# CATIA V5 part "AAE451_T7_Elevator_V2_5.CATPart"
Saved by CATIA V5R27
Part number: Elevator
Bounding box of the stored display mesh (mm): x 0 to 69.698, y -12.436 to 0.05, z -229.965 to 0
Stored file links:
  W:\AAE 451\AAE451_T7_TailAssembly_V2\AAE451_T7_Elevator_V2_5.CATPart
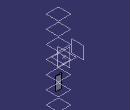
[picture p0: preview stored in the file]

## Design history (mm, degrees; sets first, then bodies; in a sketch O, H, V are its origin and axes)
Set1 "GeometryFromExcel"
  Point1: (1, 0.001, 0)
  Point2: (0.95, 0.0067, 0)
  Point3: (0.9, 0.0121, 0)
  Point4: (0.8, 0.0219, 0)
  Point5: (0.7, 0.0305, 0)
  Point6: (0.6, 0.038, 0)
  Point7: (0.5, 0.0441, 0)
  Point8: (0.4, 0.0484, 0)
  Point9: (0.3, 0.05, 0)
  Point10: (0.25, 0.0495, 0)
  Point11: (0.2, 0.0478, 0)
  Point12: (0.15, 0.0445, 0)
  Point13: (0.1, 0.039, 0)
  Point14: (0.075, 0.035, 0)
  Point15: (0.05, 0.0296, 0)
  Point16: (0.025, 0.0218, 0)
  Point17: (0.0125, 0.0158, 0)
  Point18: (0, 0, 0)
  Point19: (0.0125, -0.0158, 0)
  Point20: (0.025, -0.0218, 0)
  Point21: (0.05, -0.0296, 0)
  Point22: (0.075, -0.035, 0)
  Point23: (0.1, -0.039, 0)
  Point24: (0.15, -0.0445, 0)
  Point25: (0.2, -0.0478, 0)
  Point26: (0.25, -0.0495, 0)
  Point27: (0.3, -0.05, 0)
  Point28: (0.4, -0.0484, 0)
  Point29: (0.5, -0.0441, 0)
  Point30: (0.6, -0.038, 0)
  Point31: (0.7, -0.0305, 0)
  Point32: (0.8, -0.0219, 0)
  Point33: (0.9, -0.0121, 0)
  Point34: (0.95, -0.0067, 0)
  Point35: (1, -0.001, 0)
  Point36: (1, 0.001, 0)
  Point37: (0.95, 0.0067, 0)
  Point38: (0.9, 0.0121, 0)
  Point39: (0.8, 0.0219, 0)
  Point40: (0.7, 0.0305, 0)
  Point41: (0.6, 0.038, 0)
  Point42: (0.5, 0.0441, 0)
  Point43: (0.4, 0.0484, 0)
  Point44: (0.3, 0.05, 0)
  Point45: (0.25, 0.0495, 0)
  Point46: (0.2, 0.0478, 0)
  Point47: (0.15, 0.0445, 0)
  Point48: (0.1, 0.039, 0)
  Point49: (0.075, 0.035, 0)
  Point50: (0.05, 0.0296, 0)
  Point51: (0.025, 0.0218, 0)
  Point52: (0.0125, 0.0158, 0)
  Point53: (0, 0, 0)
  Point54: (0.0125, -0.0158, 0)
  Point55: (0.025, -0.0218, 0)
  Point56: (0.05, -0.0296, 0)
  Point57: (0.075, -0.035, 0)
  Point58: (0.1, -0.039, 0)
  Point59: (0.15, -0.0445, 0)
  Point60: (0.2, -0.0478, 0)
  Point61: (0.25, -0.0495, 0)
  Point62: (0.3, -0.05, 0)
  Point63: (0.4, -0.0484, 0)
  Point64: (0.5, -0.0441, 0)
  Point65: (0.6, -0.038, 0)
  Point66: (0.7, -0.0305, 0)
  Point67: (0.8, -0.0219, 0)
  Point68: (0.9, -0.0121, 0)
  Point69: (0.95, -0.0067, 0)
  Point70: (1, -0.001, 0)
  Curve1: Elements (Point36; Point37; Point38; Point39; Point40; Point41; Point42; Point43; Point44; Point45; Point46; Point47; Point48; Point49; Point50; Point51; Point52; Point53; Point54; Point55; Point56; Point57; Point58; Point59; Point60; Point61; Point62; Point63; Point64; Point65; Point66; Point67; Point68; Point69; Point70)
  Sketch1 on xy-plane, origin (0, 0, 0), H (1, 0, 0), V (0, 1, 0)
    projected curve E1 from edge of Curve1
    point P1 (1, 0.0011)
    line L1 (1, 0.0011) -> (1, -0.001)
    point P3 (1, 0.001)
    point P4 (1, -0.001)
    reference projected point E2 (1, 0.001) from Point1
    reference projected point E3 (1, -0.001) from Point35
    coincidence: P3 E2, P4 E3, P1 P3
Body1 (main body)
  Pad1: profile Sketch1, direction (0, 0, 1), length 1.5215, mirrored extent
  Scaling1: Reference Point40, Ratio 230, ToTransfor Pad1
  Plane1: type Offset, RefPlane yz-plane, Offset 120, reversed
  Sketch2 on xy-plane, origin (0, 0, 0), H (1, 0, 0), V (0, 1, 0)
    reference projected line E1 (69.6979, -7.2245) -> (69.698, -6.7499) from edge [face of Pad1 from Sketch1.L1 | end face of Pad1]
    line L1 (13.6994, -1.0636) -> (13.6965, -12.9194)
    projected curve E2 from edge [face of Pad1 from Sketch1.E1 | end face of Pad1]
    projected curve E3 from edge [face of Pad1 from Sketch1.E1 | end face of Pad1]
    distance E1 L1 = 56
  Pocket1: profile Sketch2, direction (0, 0, -1), through (limit type 3), opposite side through (limit type 3)
  Fillet1: radius 5, on edge [face of Pad1 from Sketch1.E1 | face of Pocket1 from Sketch2.L1]; edge [face of Pocket1 from Sketch2.L1 | face of Pad1 from Sketch1.E1]
  Sketch3 on zx-plane, origin (0, 0, 0), H (-1, 0, 0), V (0, 0, 1)
    line L1 (-135.4649, -344.945) -> (50.2623, -344.945)
    line L2 (50.2623, -344.945) -> (50.2623, -349.945)
    line L3 (50.2623, -349.945) -> (-135.4649, -349.945)
    line L4 (-135.4649, -349.945) -> (-135.4649, -344.945)
    line L5 (-146.4826, 349.945) -> (56.5582, 349.945)
    line L6 (56.5582, 349.945) -> (56.5582, 344.945)
    line L7 (56.5582, 344.945) -> (-146.4826, 344.945)
    line L8 (-146.4826, 344.945) -> (-146.4826, 349.945)
    reference projected line E1 (-69.7, 349.945) -> (160.3, 349.945) from edge [face of Pad1 from Sketch1.E1 | end face of Pad1]
    reference projected line E2 (-69.7, -349.945) -> (160.3, -349.945) from edge [start face of Pad1 | face of Pad1 from Sketch1.E1]
    distance L7 L5 = 5
    horizontal: L1 H, L3 H, L5 H, L7 H
    vertical: L2 V, L4 V, L6 V, L8 V
    coincidence: L5 E1, L3 E2
    symmetry: L7 L1 H
  Pocket2: profile Sketch3, direction (0, -1, 0), through (limit type 3)
  Sketch4 on face of Pocket1 from Sketch2.L1, origin (13.6996, -0.0033, 0), H (-0.0002, -1, 0), V (0, 0, 1)
    line L1 (6.4867, 8) -> (7.4867, 8)
    line L2 (7.4867, 8) -> (7.4867, -8)
    line L3 (7.4867, -8) -> (6.4867, -8)
    line L4 (6.4867, -8) -> (6.4867, 8)
    construction line L5 (6.9867, 7.1913) -> (6.9867, -6.7162)
    reference projected line E1 (1.5418, 344.945) -> (1.5418, -344.945) from edge [face of Pad1 from Sketch1.E1 | face of Fillet1]
    reference projected line E2 (12.4317, 344.945) -> (12.4317, -344.945) from edge [face of Fillet1 | face of Pad1 from Sketch1.E1]
    distance L4 L2 = 1
    distance L1 L3 = 16
    horizontal: L1 H, L3 H
    vertical: L2 V, L4 V
    symmetry: L3 L1 H, L4 L2 L5, E1 E2 L5
  Pocket3: profile Sketch4, direction (1, -0.0002, 0), length 13.7
  RectPattern1: of Pocket3, direction 1 instances 2, spacing 230, along zx-plane
  Mirror1: of RectPattern1, about xy-plane
  Plane2: type Offset, RefPlane face of Pocket2 from Sketch3.L7, Offset 0, reversed
  Plane3: type Offset, RefPlane face of Pocket2 from Sketch3.L1, Offset 0, reversed
  Plane4: type Offset, RefPlane Plane3, Offset 114.98
  Plane5: type Offset, RefPlane Plane4, Offset 114.98
  Plane6: type Offset, RefPlane Plane5, Offset 114.98
  Plane7: type Offset, RefPlane Plane6, Offset 114.98
  Plane8: type Offset, RefPlane Plane7, Offset 114.98
  Split1: SplitPlane Plane4
  Split2: SplitPlane Plane5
